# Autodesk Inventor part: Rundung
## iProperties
Created: 2010-04
Part Number: Rundung
Document SubType Name: Modeling
Designer: SFleischer
Density: 1 g/cm^3
Author: SFleischer
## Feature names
1. Sweeping1
2. Runde Anordnung1 [Circular Pattern]
